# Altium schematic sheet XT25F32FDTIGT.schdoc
size 127 x 101 mm
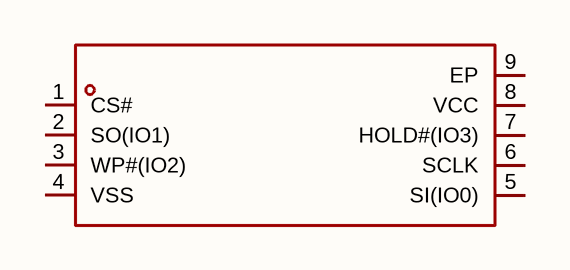
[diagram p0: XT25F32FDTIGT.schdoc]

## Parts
U?  xt25f32fdtigt  [DFN-8_L3.0-W2.0-P0.50-BL-EP_XT25XXX]  (value not drawn)

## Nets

Not connected (* = marked no-connect by the designer): U? 1(CS#) 2(SO(IO1)) 3(WP#(IO2)) 4(VSS) 5(SI(IO0)) 6(SCLK) 7(HOLD#(IO3)) 8(VCC) 9(EP)

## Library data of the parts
U? = xt25f32fdtigt: 接口类型:SPI;存储容量:32Mbit;时钟频率(fc):133MHz;; Manufacturer: XTX(芯天下); AddInBom: yes; ModelId: 12a239e5c7384371915ecb51201bf581; ModelName: USON-8_L3.0-W2.0-H0.6-P0.50; ModelTransform: 118.8974,78.74,0,90,0,0,0,0,0; Interface: SPI; Memory Size: 32Mbit; Clock Frequency: 133MHz; Voltage - Supply: 2.7V~3.6V; Standby Supply Current: 0.3uA; Program / Erase Cycles: 100000次; Page Programming Time (Tpp): 400us; Data Retention - TDR (Year): 20年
